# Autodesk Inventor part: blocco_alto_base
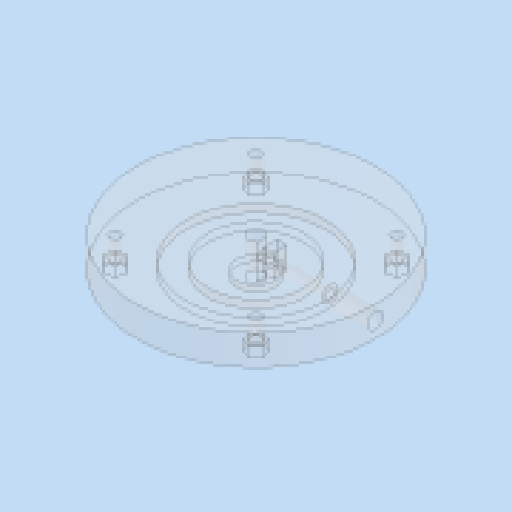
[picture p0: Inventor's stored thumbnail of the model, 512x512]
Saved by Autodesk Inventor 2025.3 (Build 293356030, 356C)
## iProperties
Created: 2026-02
Part Number: blocco_alto_base
Material: Plastica PET
Document SubType Name: Modeling
Designer: R5800u
Density: 1.541 g/cm^3
Appearance: Rosso
Author: R5800u
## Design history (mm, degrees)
sketch "Schizzo1"
  geometry: C1 r 60 at (0, 0); C2 r 4.05 at (0, 0); 1 further point
  constraints: 2 centre point, 2 coincident
  dimensions: "d0" = 120 diameter of C1; "d1" = 8.1 diameter of C2
extrude "Estrusione1" new body sketch "Schizzo1" distance "d2" = 15; taper "d3" = 0 deg
sketch "Schizzo2"
  geometry: C1 r 4.05 at (0, 0) reference; C2 r 35.05 at (0, 0); C3 r 24 at (0, 0); 1 further point
  constraints: 2 centre point, 2 coincident
  dimensions: "d4" = 70.1 diameter of C2; "d5" = 48 diameter of C3
extrude "Estrusione2" cut sketch "Schizzo2" distance "d6" = 4; taper "d7" = 0 deg
sketch "Schizzo3"
  geometry: C1 r 9.5 at (0, 0); C2 r 4.05 at (0, 0) reference; 1 further point
  constraints: 1 centre point, 1 coincident
  dimensions: "d8" = 19 diameter of C1
extrude "Estrusione3" join sketch "Schizzo3" distance "d9" = 3; taper "d10" = 0 deg
sketch "Schizzo4"
  geometry: L1 (3.15, -2.546)-(3.15, 2.546); A1 r 4.05 centre (0, 0) between (3.15, -2.546) and (3.15, 2.546) reference; 1 further point
  constraints: 2 end point, 2 point on circle, 1 vertical
  dimensions: "d11" = 3.15 distance from line of point (0, 0) L1
extrude "Estrusione4" join sketch "Schizzo4" distance "d12" = 17; taper "d13" = 0 deg
sketch "Schizzo5"
  geometry: L1 (0, 0)-(60, 0); L2 (15, 0)-(45, 0); L3 (45, 0)-(45, -10); L4 (45, -10)-(15, -10); L5 (15, -10)-(15, 0); L6 (45, 0)-(45, 10); L7 (45, 10)-(15, 10); L8 (15, 10)-(15, 0); C1 r 9.5 at (0, 0) reference; 2 further points
  constraints: 16 end point, 2 horizontal, 2 parallel, 2 symmetric about line, 1 horizontal alignment, 1 perpendicular, 1 point on line, 1 other
  dimensions: "d14" = 30 distance of L3.end L4.end; "d15" = 10 distance of L2.end L3.end; "d16" = 15 distance from line of point (0, 0) L5
extrude "Estrusione5" cut sketch "Schizzo5" distance "d17" = 10; taper "d18" = 0 deg
sketch "Schizzo6"
  geometry: L1 (0, 0)-(5.091, 0) reference; L2 (0, -17)-(0, 0) reference; L3 (5.091, -17)-(0, -17) reference; L4 (5.091, 0)-(5.091, -17) reference; L5 (2.546, 0)-(2.546, -7); 2 further points
  constraints: 2 end point, 1 coincident, 1 midpoint, 1 vertical
  dimensions: "d19" = 7 distance of L5.start L5.end
hole "Foro1" sketch "Schizzo6" at (2.546, -7) diameter "d20" = 4.3; stored, may be unused: countersink angle "d24" = 90 deg, drill point angle "d26" = 118 deg; dims "d21" = 6, "d22" = 9.4, "d23" = 2, "d25" = 8
node "Piano di lavoro1"
sketch "Schizzo7"
  geometry: L1 (-0.954, -3.5)-(6.046, -3.5); L2 (6.046, -3.5)-(6.046, -10.5); L3 (6.046, -10.5)-(-0.954, -10.5); L4 (-0.954, -10.5)-(-0.954, -3.5); L5 (-0.954, -3.5)-(6.046, -10.5); L6 (6.046, -3.5)-(-0.954, -10.5); L7 (62.546, 0)-(-57.454, 0) reference; L8 (-0.954, -3.5)-(6.046, -3.5); L9 (6.046, -3.5)-(6.046, 0); L10 (6.046, 0)-(-0.954, 0); L11 (-0.954, 0)-(-0.954, -3.5); L12 (-0.954, -10.5)-(6.046, -10.5); L13 (6.046, -10.5)-(6.046, -11); L14 (6.046, -11)-(-0.954, -11); L15 (-0.954, -11)-(-0.954, -10.5); C1 r 2.15 at (2.546, -7) reference; 4 further points
  constraints: 28 end point, 6 parallel, 3 horizontal, 3 perpendicular, 2 midpoint, 1 point on line
  dimensions: "d28" = 7 distance of L2.end L3.end; "d29" = 7 distance of L1.end L2.end; "d32" = 0.5 distance of L12.end L13.end
extrude "Estrusione6" cut sketch "Schizzo7" distance "d30" = 5; taper "d31" = 0 deg
node "Piano di lavoro2"
sketch "Schizzo8"
  geometry: C1 r 4 at (2.546, -7); 2 further points
  constraints: 1 centre point, 1 other
  dimensions: "d34" = 8 diameter of C1
extrude "Estrusione7" cut sketch "Schizzo8" distance "d35" = 23; taper "d36" = 0 deg
sketch "Schizzo9" dims "d38" = 100
  geometry: L1 (0, 0)-(-42.426, 42.426); L2 (0, 0)-(60, 0); 3 further points
  constraints: 4 end point, 1 coincident, 1 equal length, 1 horizontal, 1 point on line, 5 other
  dimensions: "d37" = 135 deg angle of L2 L1
hole "Foro2" sketch "Schizzo9" at (-35.355, 35.355) diameter "d39" = 5.3; stored, may be unused: countersink angle "d43" = 90 deg, drill point angle "d45" = 118 deg; dims "d40" = 6, "d41" = 10.4, "d42" = 2, "d44" = 8
sketch "Schizzo10" dims "d46" = 9.4
  geometry: L1 (-34.139, 30.815)-(-38.679, 32.032); L2 (-38.679, 32.032)-(-39.895, 36.572); L3 (-39.895, 36.572)-(-36.572, 39.895); L4 (-36.572, 39.895)-(-32.032, 38.679); L5 (-32.032, 38.679)-(-30.815, 34.139); L6 (-30.815, 34.139)-(-34.139, 30.815); L7 (0, 0)-(-32.477, 32.477); C1 r 2.65 at (-35.355, 35.355) reference; A1 r 4.05 centre (0, 0) between (3.15, 2.546) and (3.15, -2.546) reference; 3 further points
  constraints: 14 end point, 2 coincident, 1 midpoint, 1 perpendicular, 16 other
extrude "Estrusione8" cut sketch "Schizzo10" distance "d47" = 5; taper "d48" = 0 deg
pattern_circular "Serie circolare1" dims "d50" = 360 deg
node "Solido1"
node "Linea chiusa proiettata1"
other parameters: "d27" = -4, "d33" = -48
